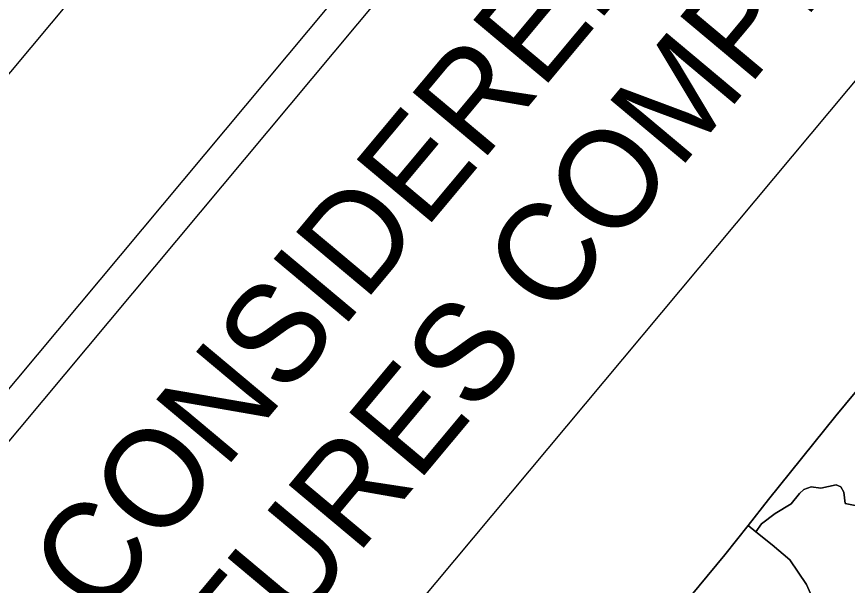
# Model space of a CAD drawing. Extents: x 555292 to 2368606, y 503623 to 1171444.
# Drawn here: x 2360657.5 to 2360914.2, y 1167734.3 to 1167909.8 of the extents above; entities that cross this region are included whole.
import ezdxf

# ---------------------------------------------------------------- set-up
doc = ezdxf.new("R2010")
doc.units = 0
for name, color, linetype in [('Default', 7, 'Continuous'), ('Old_Level_19', 7, 'Continuous'), ('Sheet Title CELL', 7, 'Continuous')]:
    doc.layers.add(name, color=color, linetype=linetype)

msp = doc.modelspace()

# ---------------------------------------------------------------- linework, layer by layer
at = {"layer": 'Default'}
for p, q in [((2360346.12, 1167409.32), (2361051.13, 1168252.19)), ((2361150.15, 1168169.37), (2360445.14, 1167326.5))]:
    msp.add_line(p, q, dxfattribs=at)
at = {"layer": 'Old_Level_19'}
for points in [[(2360919.6, 1167797.45), (2360910.59, 1167786.66), (2360889.83, 1167760.83), (2360883.48, 1167752.75), (2360876.28, 1167743.79), (2360862.93, 1167727.56)], [(2360910.59, 1167786.66), (2360919.6, 1167797.45)], [(2360918.16, 1167758.68), (2360913.53, 1167759.61), (2360913.09, 1167763.07), (2360912.16, 1167764.7), (2360910.67, 1167765.29), (2360906, 1167764.35), (2360902.94, 1167764.76), (2360900.76, 1167763.92), (2360899.39, 1167762.63), (2360896.84, 1167759.48), (2360891.83, 1167756.53), (2360887.64, 1167753.28), (2360885.94, 1167750.84), (2360883.48, 1167752.75), (2360889.83, 1167760.83), (2360910.59, 1167786.66)], [(2360914.84, 1167729.51), (2360912.24, 1167728.86), (2360910.81, 1167729.36), (2360908.13, 1167727.94), (2360907.83, 1167726.41), (2360906.6, 1167725.65), (2360905.26, 1167725.37), (2360903.54, 1167730.16), (2360901.55, 1167734.59), (2360896.38, 1167742.15), (2360890.92, 1167746.79), (2360885.94, 1167750.84), (2360887.64, 1167753.28), (2360891.83, 1167756.53), (2360896.84, 1167759.48), (2360899.39, 1167762.63), (2360900.76, 1167763.92), (2360902.94, 1167764.76), (2360906, 1167764.35), (2360910.67, 1167765.29), (2360912.16, 1167764.7), (2360913.09, 1167763.07), (2360913.53, 1167759.61), (2360918.16, 1167758.68)], [(2360876.28, 1167743.79), (2360883.48, 1167752.75), (2360885.94, 1167750.84), (2360890.92, 1167746.79), (2360896.38, 1167742.15), (2360901.55, 1167734.59), (2360903.54, 1167730.16), (2360905.26, 1167725.37), (2360902.12, 1167724.84), (2360897.89, 1167720.81), (2360896.56, 1167719.83), (2360895.05, 1167720.25), (2360894.01, 1167719.78), (2360892.55, 1167718.26), (2360888.52, 1167714.69), (2360886.17, 1167711.83), (2360885.4, 1167711.88), (2360883.87, 1167710.29), (2360882.87, 1167714.72), (2360881.9, 1167716.03), (2360862.93, 1167727.56), (2360876.28, 1167743.79)]]:
    msp.add_lwpolyline(points, dxfattribs=at)
at = {"layer": 'Sheet Title CELL'}
msp.add_lwpolyline([(2360200.37, 1167251.29), (2361082.56, 1168305.98), (2361034.66, 1168346.04), (2360152.43, 1167291.39), (2360104.54, 1167331.45), (2360986.72, 1168386.14), (2360938.78, 1168426.24), (2360056.64, 1167371.6), (2360008.61, 1167411.69), (2360890.79, 1168466.38), (2360842.85, 1168506.48), (2359960.67, 1167451.79), (2359912.77, 1167491.85), (2360794.91, 1168546.58), (2360747.02, 1168586.64), (2359864.83, 1167531.95), (2359816.89, 1167572.05), (2360699.08, 1168626.74), (2360651.09, 1168666.88), (2359768.91, 1167612.19)], dxfattribs=at)

# ---------------------------------------------------------------- texts
at = {"layer": 'Default'}
for s, p in [('DOCUMENT NOT CONSIDERED FINAL', (2360463.97, 1167461.64)), ('UNLESS ALL SIGNATURES COMPLETED', (2360483.18, 1167409.26))]:
    msp.add_text(s, height=30.2128, rotation=50.0895, dxfattribs=at).set_placement(p)

doc.saveas('drawing.dxf')
